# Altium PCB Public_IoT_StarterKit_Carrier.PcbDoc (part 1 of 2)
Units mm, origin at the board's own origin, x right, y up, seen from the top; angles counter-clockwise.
Board outline 84.62 x 84.55 mm, 4 copper layers (Top, PWR, MID, Bottom), stack 1.612 mm thick; 85 components, 101 nets, 416 pads, 114 vias.
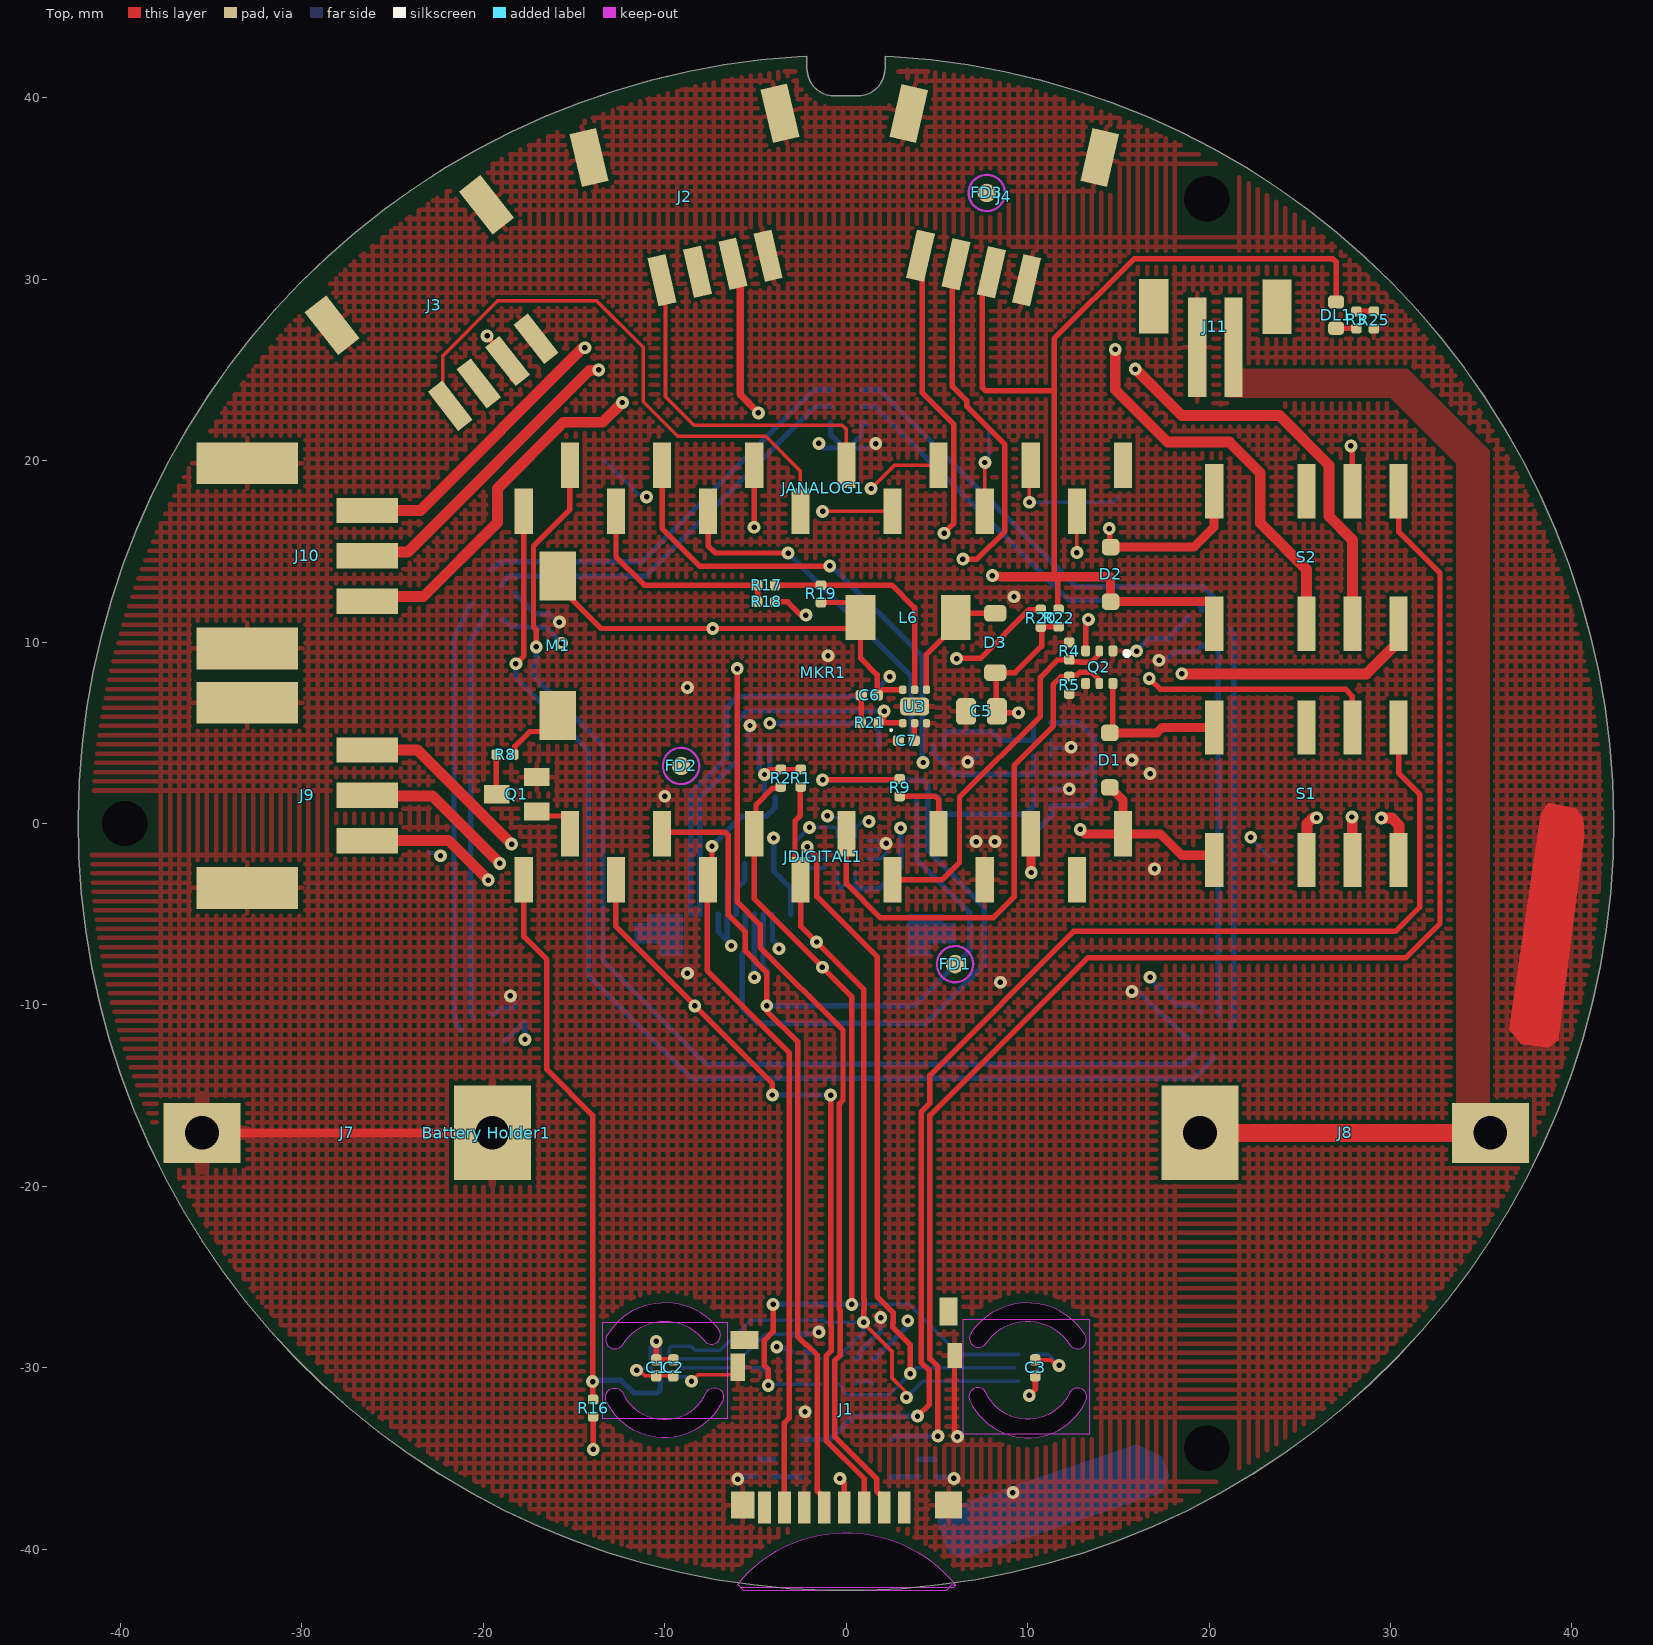
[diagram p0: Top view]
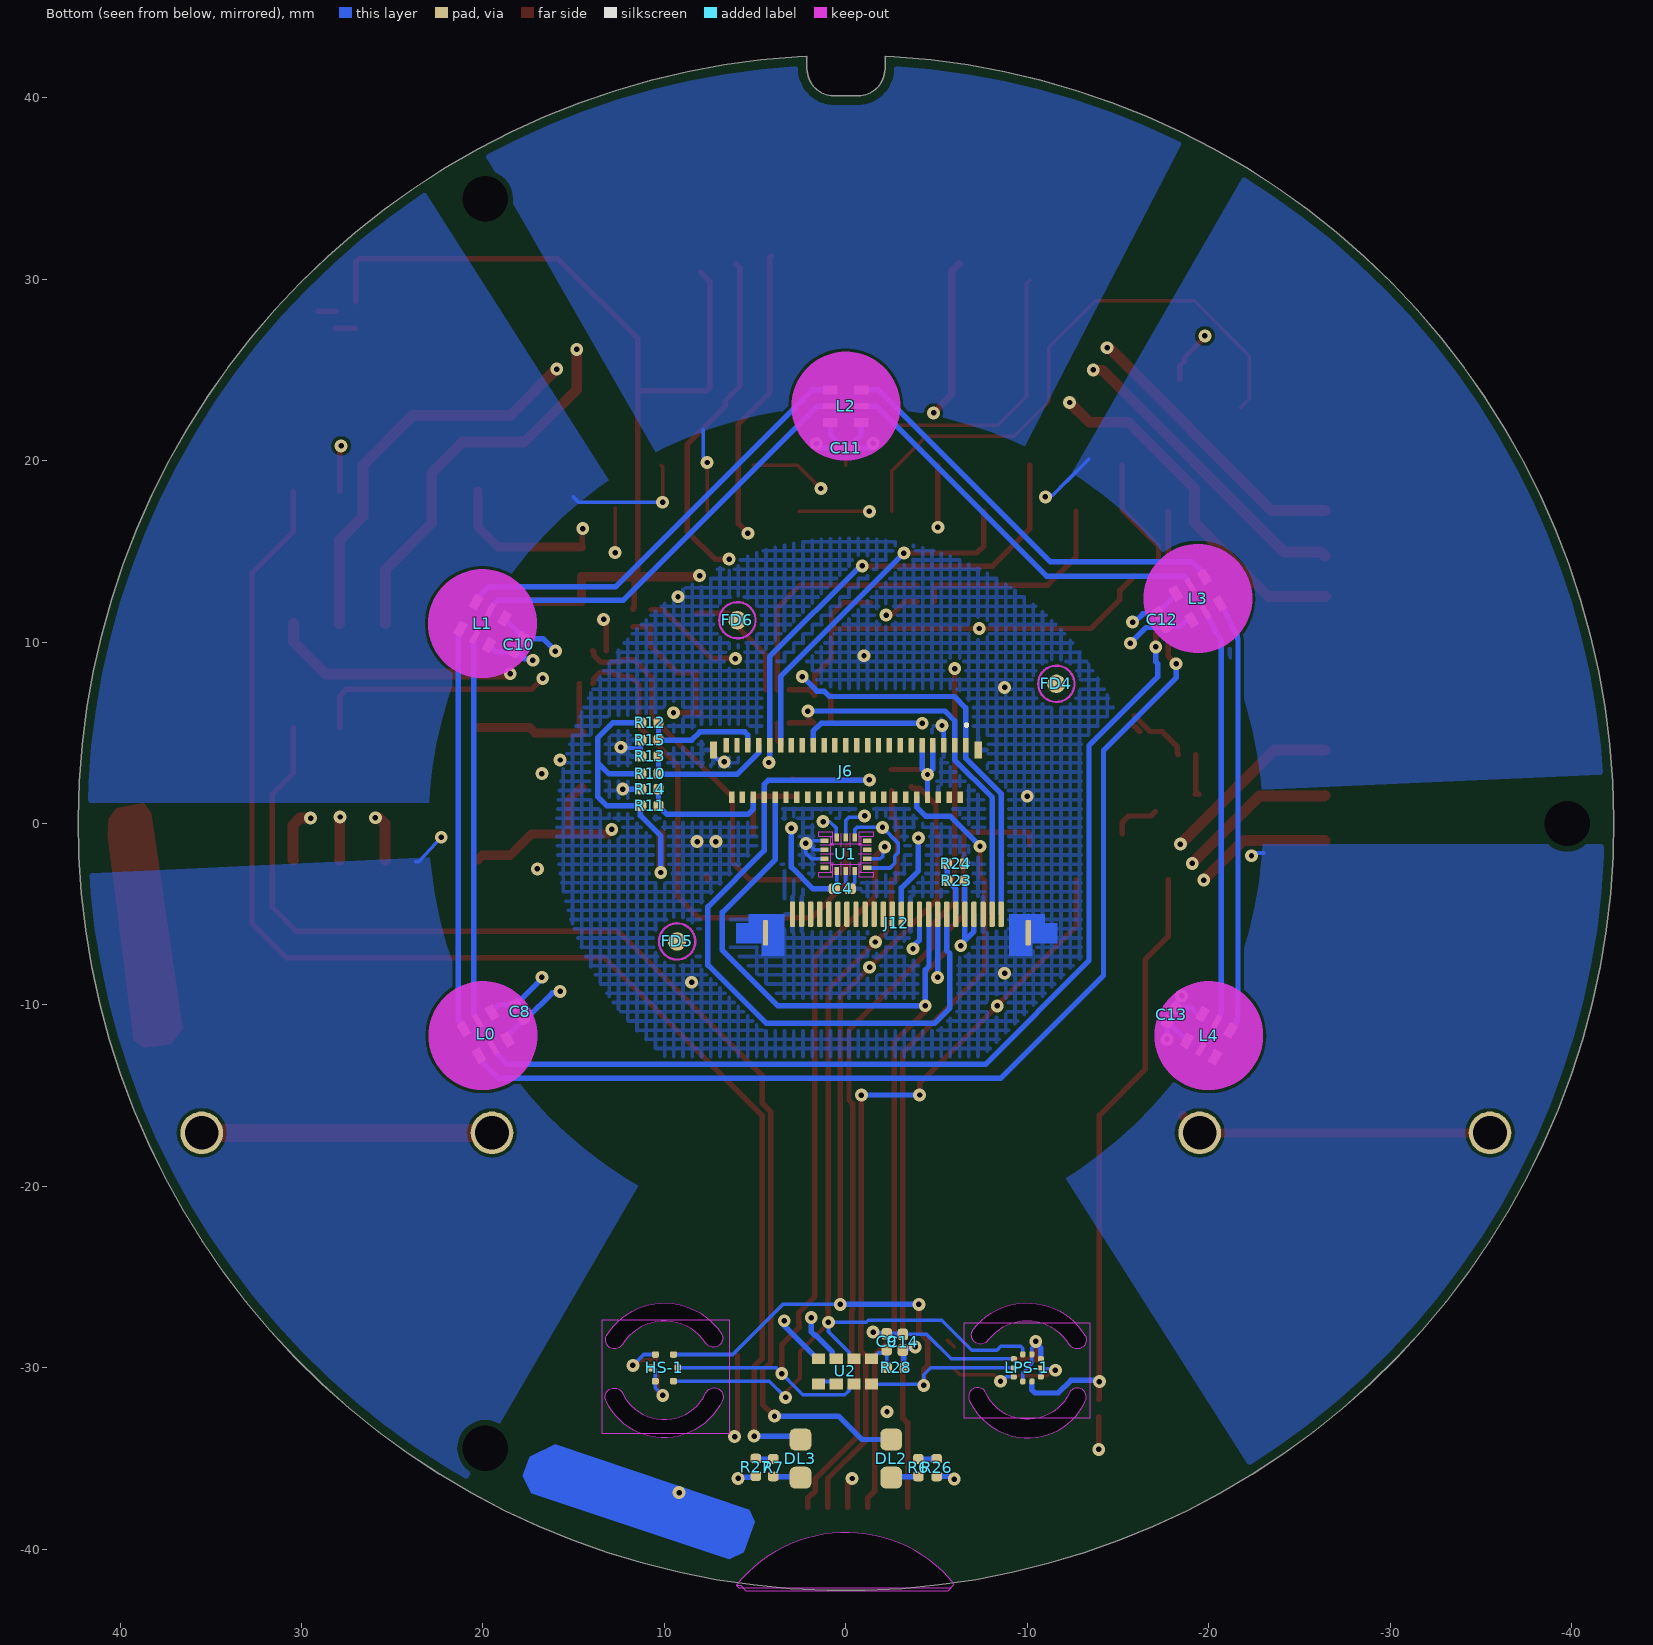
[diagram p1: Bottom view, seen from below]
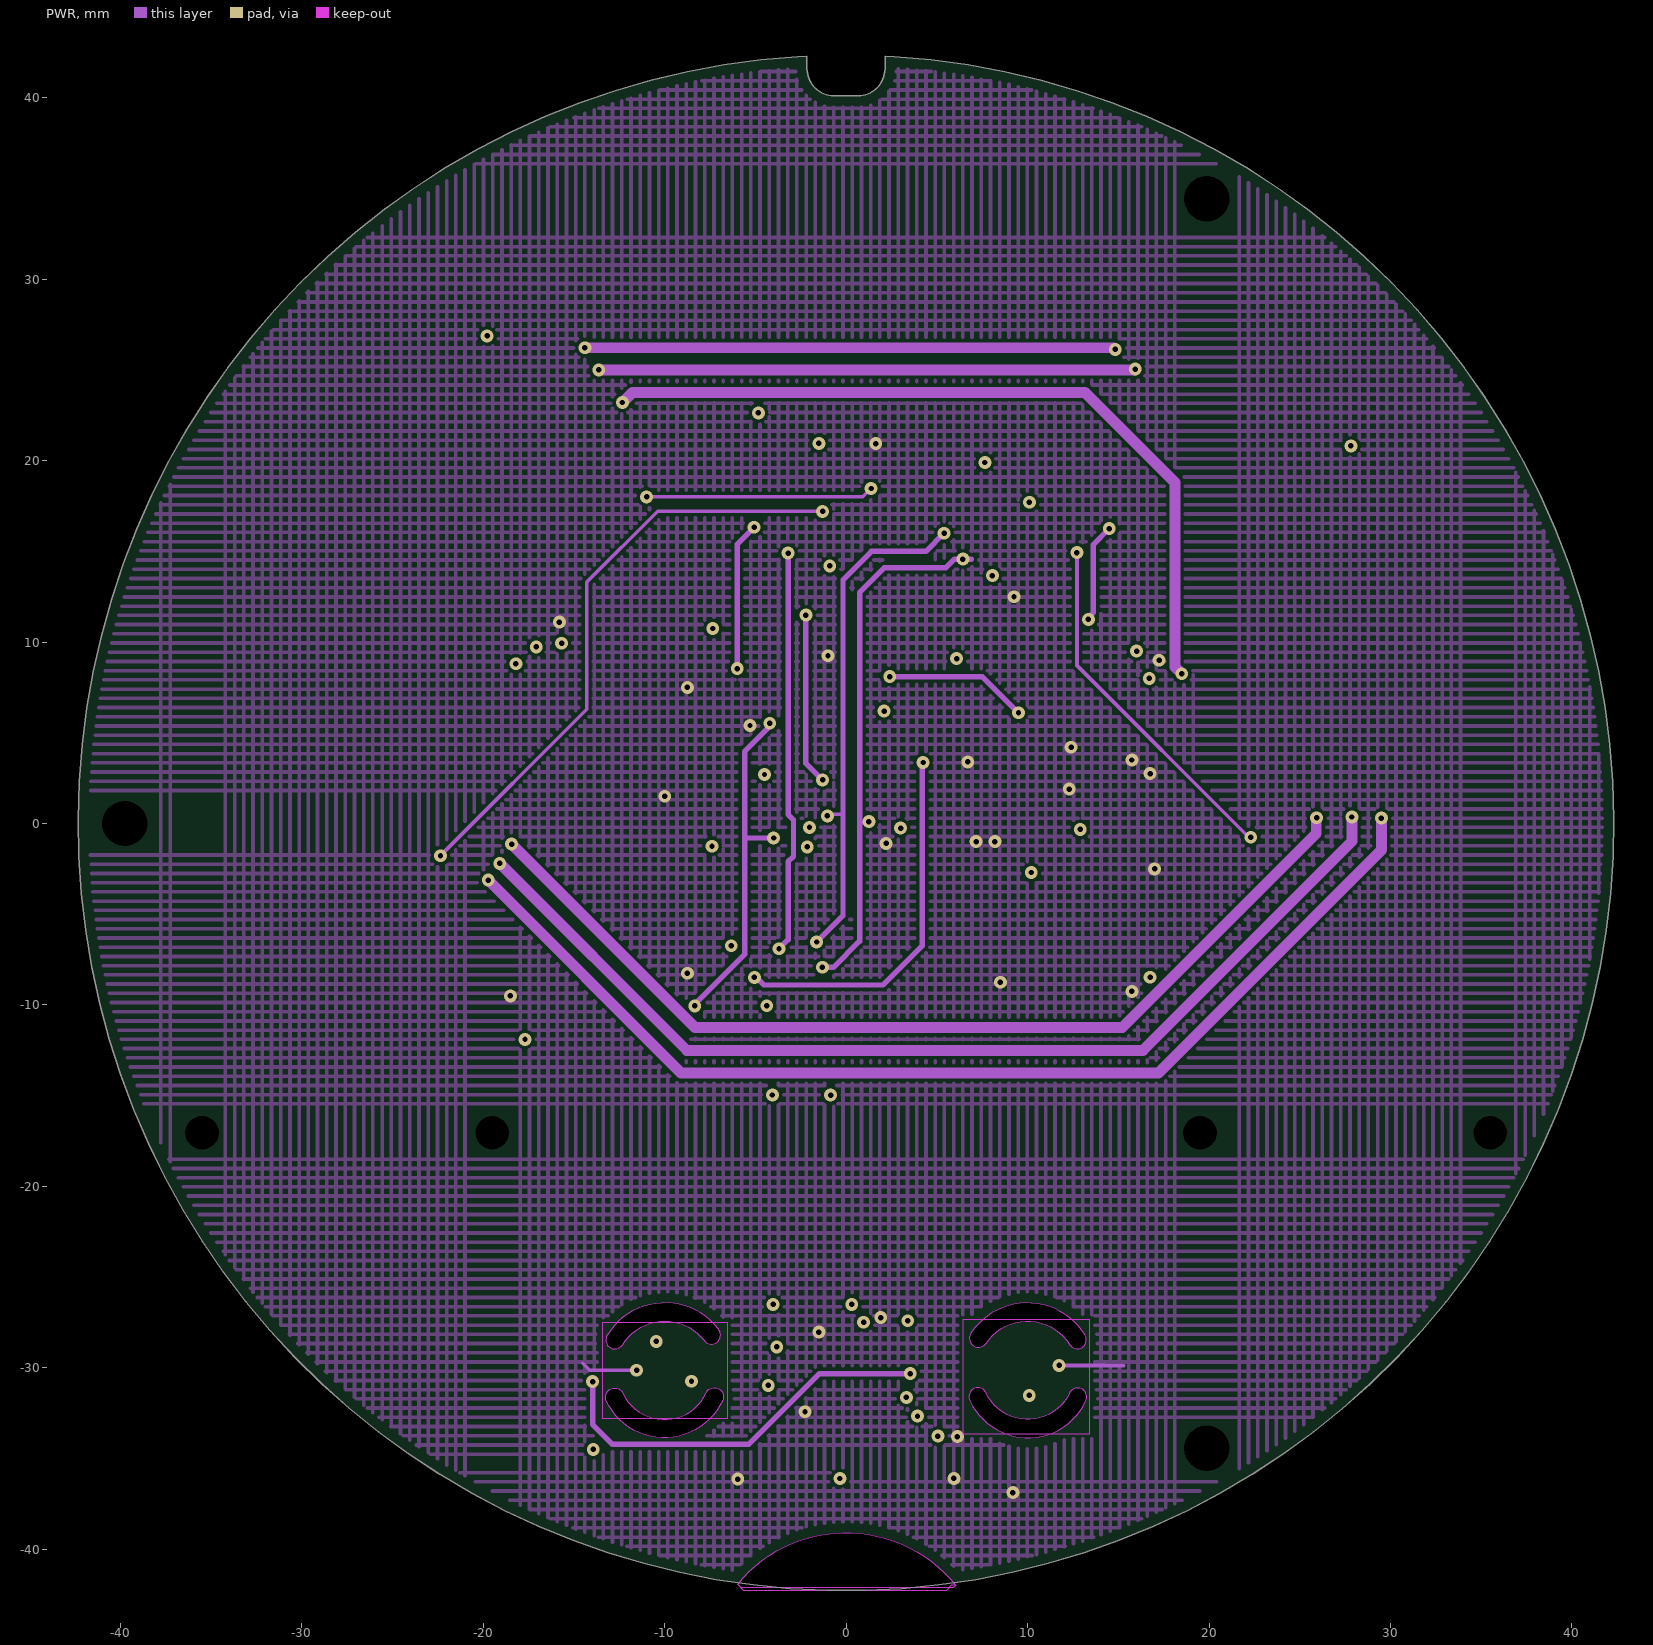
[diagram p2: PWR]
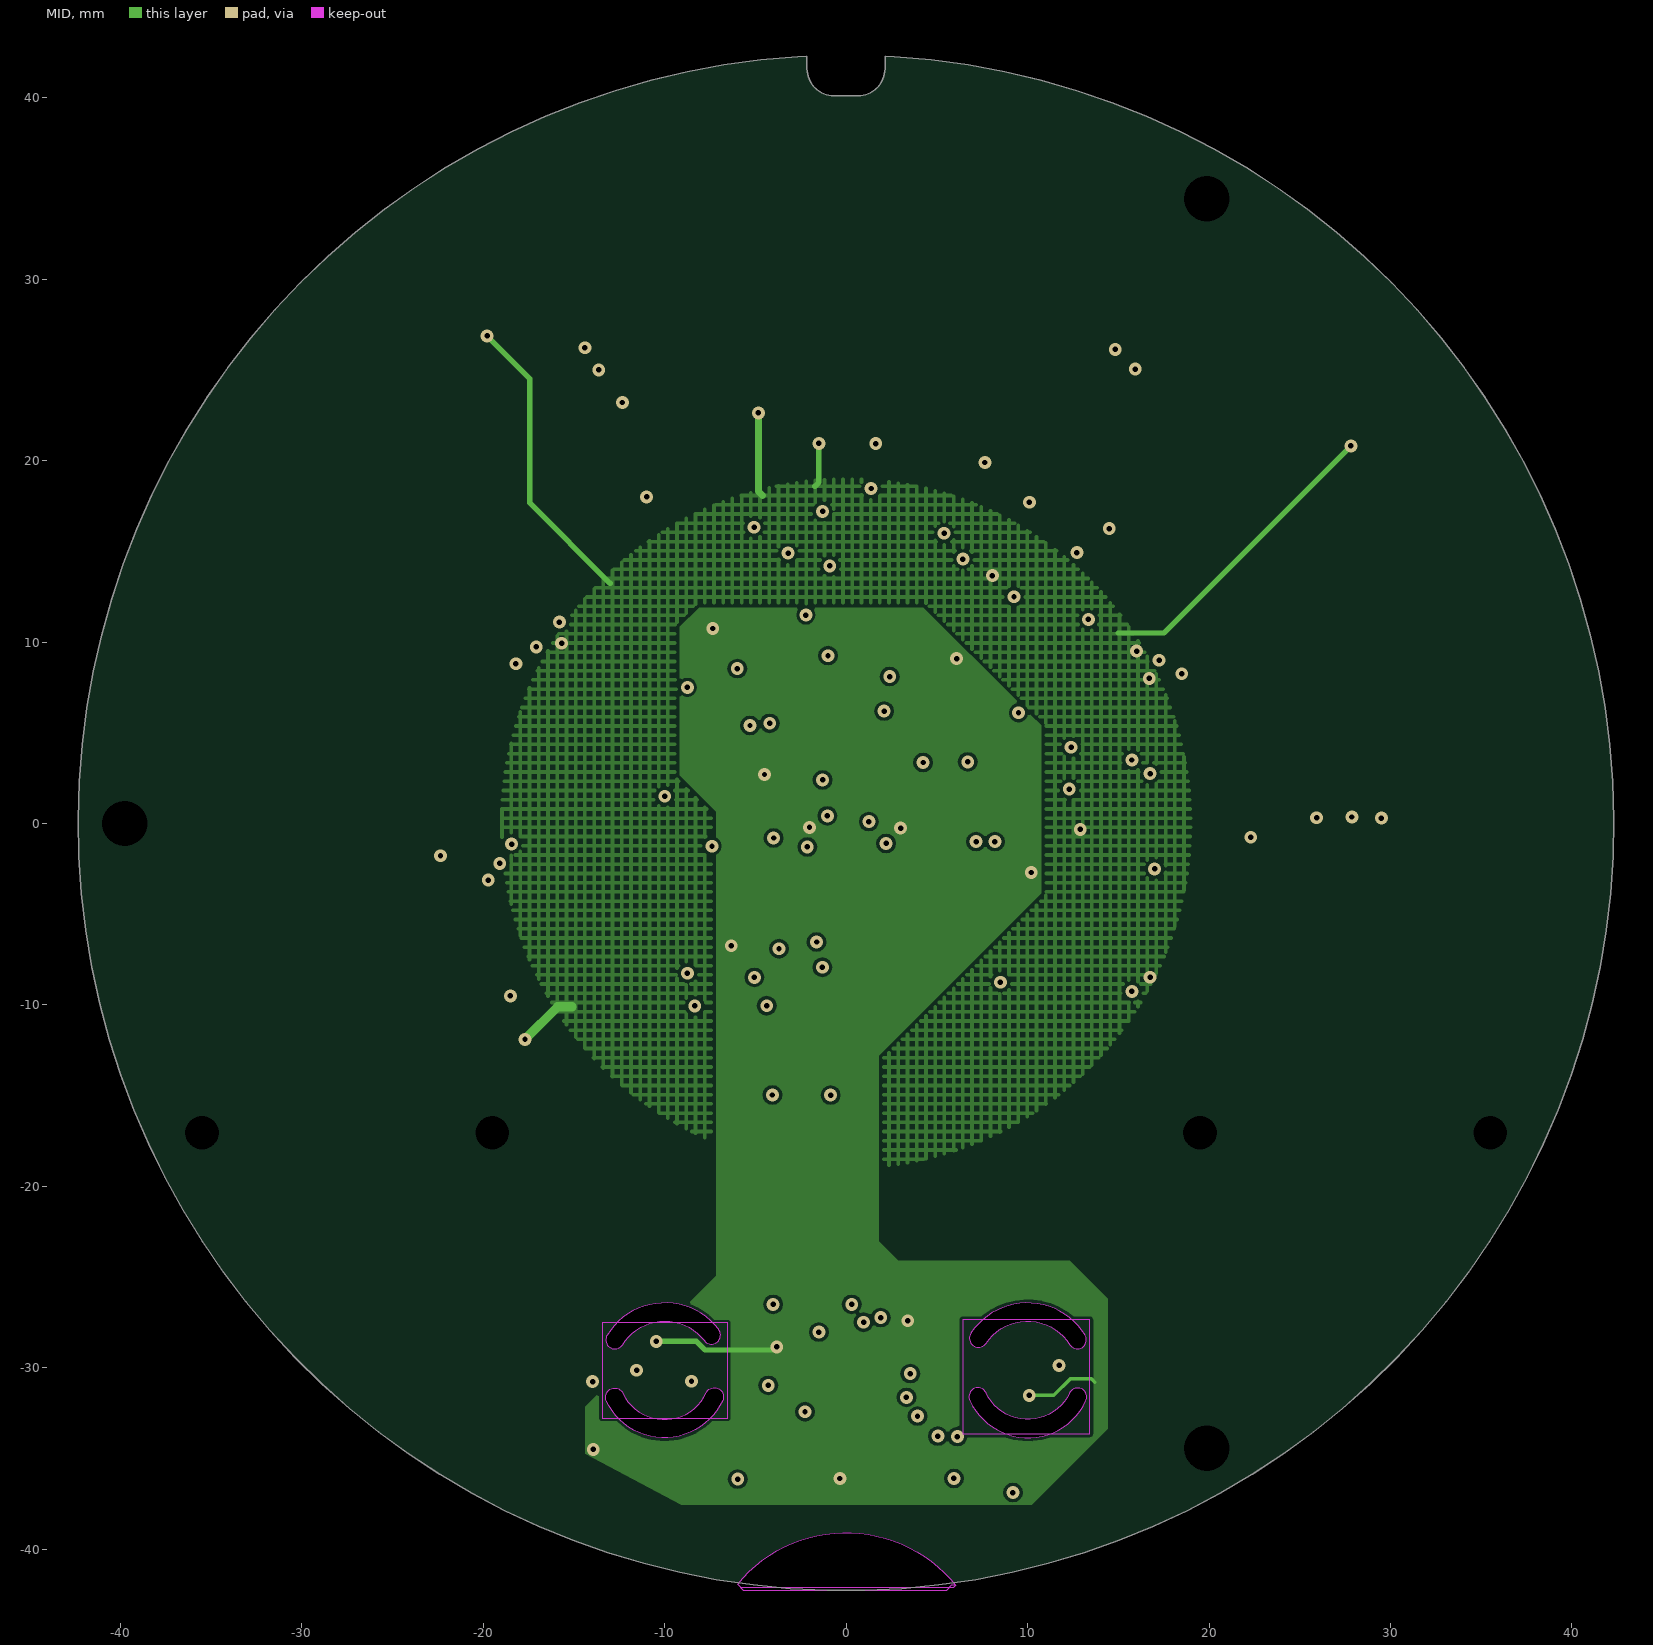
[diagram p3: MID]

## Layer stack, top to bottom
Top Solder: solder mask 0.01, Solder Resist, Dk 3.5
Top: signal copper 0.035
Dielectric 1: prepreg 0.356, FR-4, Dk 4.1
PWR: signal copper 0.035
Dielectric3: core 0.76, FR-4, Dk 4.8
MID: signal copper 0.035
Dielectric2: prepreg 0.356, FR-4, Dk 4.1
Bottom: signal copper 0.035
Bottom Solder: solder mask 0.0102, Solder Resist, Dk 3.5

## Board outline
-39.256,-15.774 -39.976,-13.853 -40.602,-11.9 -41.133,-9.918 -41.567,-7.914 -41.903,-5.89 -42.141,-3.853 -42.28,-1.806 -42.32,0.245 -42.26,2.295 -42.101,4.34 -41.843,6.375 -41.487,8.395 -41.033,10.396 -40.483,12.372 -39.837,14.319 -39.098,16.232 -38.267,18.108 -37.346,19.941 -36.338,21.727 -35.244,23.462 -34.067,25.142 -32.81,26.764 -31.477,28.322 -30.069,29.814 -28.59,31.236 -27.045,32.584 -25.435,33.856 -23.766,35.049 -22.042,36.159 -20.265,37.185 -18.441,38.123 -16.573,38.971 -14.667,39.728 -12.726,40.392 -10.755,40.961 -8.759,41.434 -6.743,41.809 -4.71,42.087 -2.667,42.265 -2.161,42.285 -2.161,41.593 -2.154,41.446 -2.099,41.169 -1.986,40.897 -1.822,40.652 -1.614,40.444 -1.369,40.28 -1.097,40.167 -0.82,40.112 -0.673,40.105 0.657,40.105 0.804,40.112 1.081,40.167 1.353,40.28 1.598,40.444 1.806,40.652 1.97,40.897 2.083,41.169 2.138,41.446 2.145,41.593 2.145,42.285 2.65,42.265 4.694,42.087 6.726,41.809 8.743,41.434 10.739,40.961 12.71,40.392 14.651,39.728 16.557,38.971 18.425,38.123 20.249,37.185 22.025,36.159 23.75,35.049 25.419,33.856 27.028,32.584 28.574,31.236 30.053,29.814 31.46,28.322 32.794,26.764 34.051,25.142 35.228,23.462 36.322,21.727 37.33,19.941 38.251,18.108 39.082,16.232 39.821,14.319 40.466,12.372 41.017,10.396 41.47,8.395 41.827,6.375 42.085,4.34 42.244,2.295 42.304,0.245 42.264,-1.806 42.125,-3.853 41.887,-5.89 41.551,-7.914 41.117,-9.918 40.586,-11.9 39.96,-13.853 39.24,-15.774 38.427,-17.657 37.525,-19.499 36.534,-21.295 35.457,-23.041 34.297,-24.733 33.056,-26.367 31.738,-27.938 30.344,-29.444 28.88,-30.88 27.348,-32.244 25.751,-33.532 24.094,-34.741 22.38,-35.868 20.614,-36.911 18.799,-37.867 16.94,-38.734 15.041,-39.509 13.107,-40.192 11.142,-40.781 9.15,-41.273 7.138,-41.668 5.108,-41.966 3.066,-42.164 1.018,-42.264 -1.034,-42.264 -3.083,-42.164 -5.124,-41.966 -7.154,-41.668 -9.167,-41.273 -11.158,-40.781 -13.123,-40.192 -15.057,-39.509 -16.956,-38.734 -18.815,-37.867 -20.63,-36.911 -22.396,-35.868 -24.11,-34.741 -25.767,-33.532 -27.364,-32.244 -28.896,-30.88 -30.361,-29.444 -31.754,-27.938 -33.072,-26.367 -34.313,-24.733 -35.473,-23.041 -36.55,-21.295 -37.541,-19.499 -38.443,-17.657
cut-out: -13.171,-28.197 ccw(c-12.745,-28.459) -12.319,-28.722 cw(c-9.991,-30.158) -7.821,-28.492 ccw(c-7.424,-28.187) -6.924,-28.187 ccw(c-7.424,-28.187) -7.027,-27.882 ccw(c-9.991,-30.158)
cut-out: -6.808,-31.803 cw(c-10.016,-30.312) -13.214,-31.825 cw(c-12.761,-31.611) -13.262,-31.611 cw(c-12.761,-31.611) -12.309,-31.397 ccw(c-10.016,-30.312) -7.715,-31.381 cw(c-7.262,-31.592)
cut-out: 6.808,-31.803 ccw(c10.016,-30.312) 13.214,-31.825 ccw(c12.761,-31.611) 13.262,-31.611 ccw(c12.761,-31.611) 12.309,-31.397 cw(c10.016,-30.312) 7.715,-31.381 ccw(c7.262,-31.592)
cut-out: 6.876,-28.094 ccw(c7.293,-28.37) 7.71,-28.647 cw(c9.991,-30.158) 12.319,-28.722 ccw(c12.745,-28.459) 13.245,-28.459 ccw(c12.745,-28.459) 13.171,-28.197 ccw(c9.991,-30.158)
cut-out: -5.63,-42.274 -5.983,-41.921 cw(c0,-46.8) 6.037,-41.989 5.805,-41.989 5.519,-42.274
cut-out: -5.783,-42.12 -5.983,-41.921 cw(c0,-46.8) 6.037,-41.989 5.896,-42.13

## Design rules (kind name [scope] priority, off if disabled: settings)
BoardOutlineClearance BoardOutlineClearance_1 [IsPolygon] p1: gap=0.5 ignorepadtopadclearanceinfootprint=FALSE
Clearance "Clearance (Same Net)" [All] p1 off: gap=0.178 ignorepadtopadclearanceinfootprint=TRUE except(0.152: SMDPad-SMDPad SMDPad-THPad SMDPad-Via)
Clearance [All] p2: gap=0.178 ignorepadtopadclearanceinfootprint=TRUE except(0.3: THPad-Fill THPad-Poly THPad-Region)
HoleSize [All] p1: absolutevalues=TRUE maxlimit=2540 minlimit=0.3 maxpercent=80.000 minpercent=20.000
HoleToHoleClearance mdDrill [All] p1: gap=0.254 allowstackedmicrovias=TRUE
MinimumSolderMaskSliver [All] p1 off: minsoldermaskwidth=0.1
PasteMaskExpansion Expansion_SMDPaste_OFF [InPadClass('SMDPaste_OFF')] p1: expansion=0
PasteMaskExpansion mlMinCreamFrame [All] p2: expansion=0
PolygonConnect PolygonConnect_For_PolygonThermal_ON_Width120000_Gap100000 [InPolygonClass('PolygonThermal_ON_Width120000_Gap100000')] p1: connectstyle=Relief reliefconductorwidth=0.305 reliefentries=4 polygonreliefangle="90 Angle" airgapwidth=0.254
PolygonConnect PolygonConnect_For_PolygonThermal_OFF [InPolygonClass('PolygonThermal_OFF')] p2: connectstyle=Direct reliefconductorwidth=0.254 reliefentries=4 polygonreliefangle="90 Angle" airgapwidth=0.254
PolygonConnect PolygonConnect_For_PolygonThermal_ON_Width160000_Gap100000 [InPolygonClass('PolygonThermal_ON_Width160000_Gap100000')] p3: connectstyle=Relief reliefconductorwidth=0.406 reliefentries=4 polygonreliefangle="90 Angle" airgapwidth=0.254
PolygonConnect ThermalVias [IsVia] p4: connectstyle=Direct reliefconductorwidth=0.254 reliefentries=4 polygonreliefangle="90 Angle" airgapwidth=0.254
PolygonConnect [All] p5: connectstyle=Relief reliefconductorwidth=0.254 reliefentries=4 polygonreliefangle="90 Angle" airgapwidth=0.254
RoomDefinition SD-Card [InComponentClass('SD-Card')] p1 off: confinementstyle=ConfineIn formatcopy=TRUE lockcomponents=FALSE outline -290.242,-353.781 -239.442,-353.781 -239.442,-328.381 -290.242,-328.381
RoomDefinition "SC_capacitive buttons_6" [InComponentClass('SC_capacitive buttons_6')] p2 off: confinementstyle=ConfineIn formatcopy=TRUE lockcomponents=FALSE outline -290.242,-353.781 -239.442,-353.781 -239.442,-328.381 -290.242,-328.381
RoomDefinition Relays [InComponentClass('Relays')] p3 off: confinementstyle=ConfineIn formatcopy=TRUE lockcomponents=FALSE outline -290.242,-353.781 -239.442,-353.781 -239.442,-328.381 -290.242,-328.381
RoomDefinition OLED [InComponentClass('OLED')] p4 off: confinementstyle=ConfineIn formatcopy=TRUE lockcomponents=FALSE outline 43.957,-34.181 69.057,-34.181 69.057,-29.981 43.957,-29.981
RoomDefinition APDS-9306-065 [InComponentClass('APDS-9306-065')] p5 off: confinementstyle=ConfineIn formatcopy=TRUE lockcomponents=FALSE outline 43.957,-41.381 48.357,-41.381 48.357,-35.581 43.957,-35.581
RoomDefinition ABT-461-RC [InComponentClass('ABT-461-RC')] p6 off: confinementstyle=ConfineIn formatcopy=TRUE lockcomponents=FALSE outline -290.242,-353.781 -239.442,-353.781 -239.442,-328.381 -290.242,-328.381
RoomDefinition "IMU sensor" [InComponentClass('IMU sensor')] p7 off: confinementstyle=ConfineIn formatcopy=TRUE lockcomponents=FALSE outline -147.842,-244.081 -144.042,-244.081 -144.042,-239.481 -147.842,-239.481
RoomDefinition Controller [InComponentClass('Controller')] p8 off: confinementstyle=ConfineIn formatcopy=TRUE lockcomponents=FALSE outline -290.242,-353.781 -239.442,-353.781 -239.442,-328.381 -290.242,-328.381
RoomDefinition "Humidity/Temp Sensor" [InComponentClass('Humidity/Temp Sensor')] p9 off: confinementstyle=ConfineIn formatcopy=TRUE lockcomponents=FALSE outline -231.142,-341.181 -228.342,-341.181 -228.342,-337.181 -231.142,-337.181
RoomDefinition "Barometric Sensor" [InComponentClass('Barometric Sensor')] p10 off: confinementstyle=ConfineIn formatcopy=TRUE lockcomponents=FALSE outline -231.142,-346.481 -225.142,-346.481 -225.142,-342.481 -231.142,-342.481
RoomDefinition TOP [InComponentClass('TOP')] p11 off: confinementstyle=ConfineIn formatcopy=TRUE lockcomponents=FALSE outline -278.142,-341.681 -252.442,-341.681 -252.442,-273.381 -278.142,-273.381
RoutingVias [All] p1: holewidth=0.3 width=0.706 viastyle="Through Hole" minholewidth=0.3 minwidth=0.706 maxholewidth=2.54 maxwidth=2.54
SilkToSilkClearance [All] p1 off: silktosilkclearance=0.254
SilkToSolderMaskClearance [IsPad] p1 off: minsilkscreentomaskgap=0.1 clearancetoexposedcopper=TRUE
SolderMaskExpansion Expansion_SMDSolder_OFF [InPadClass('SMDSolder_OFF')] p1: expansion=0 istentingtop=FALSE
SolderMaskExpansion mlMinStopFrame [All] p2: expansion=0.1 istentingtop=FALSE
Width [All] p1: maxlimit=254 minlimit=0.2 preferedwidth=0.3
24 further rules are at their usual default settings.

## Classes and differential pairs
component class SD-Card: J1
component class OLED: C5 C6 C7 D3 J6 J12 L6 R10 R11 R12 R13 R14 R15 R19 R20 R21 R22 R23 R24 U3
component class APDS-9306-065: C9 C14 R28 U2
component class ABT-461-RC: M1 Q1 R8
component class TOP: "Battery Holder1" DL1 FD1 FD2 FD3 FD4 FD5 FD6 J2 J3 J4 J7 J8 J11 R3 R9 R16 R17 R18 R25
component class "IMU sensor": C4 U1
component class Relays: D1 D2 DL2 DL3 J9 J10 Q2 R4 R5 R6 R7 R26 R27 S1 S2
component class "Humidity/Temp Sensor": C3 HS-1
component class "Barometric Sensor": C1 C2 LPS-1
component class "SC_capacitive buttons_6": C8 C10 C11 C12 C13 L0 L1 L2 L3 L4
component class Controller: JANALOG1 JDIGITAL1 MKR1 R1 R2

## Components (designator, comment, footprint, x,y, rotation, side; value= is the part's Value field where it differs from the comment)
"Battery Holder1" "Battery Holder" "Battery Holder-Footprint-1" -19.834,-17.049 r0 top
C1 "C0402C103K3RACTU" CAP-0402 -10.465,-30 r270 top value=10nF
C2 "GRM155R60J475ME47D" CAP-0402 -9.519,-30 r90 top value=4.7µF
C3 "C0402C104K3PACTU" CAP-0402 10.425,-30 r270 top value=100nF
C4 "C0402C104K3PACTU" CAP-0402 0.2,-3.6 r0 bottom value=100nF
C5 "GCM21BC72A105KE36L" CAP-0805 7.458,6.178 r0 top value=1µF
C6 "C0402C105M9PACTU" CAP-0402 1.273,7.073 r0 top value=1µF
C7 "C0402C224K9PACTU" CAP-0402 3.319,4.57 r0 top value=220nF
C8 "C0402C104K3PACTU" CAP-0402 17.98,-10.38 r60 bottom value=100nF
C9 "C0402C105K4PACTU" CAP-0402 -2.25,-28.565 r270 bottom value=1µF
C10 "C0402C104K3PACTU" CAP-0402 18.034,9.844 r120 bottom value=100nF
C11 "C0402C104K3PACTU" CAP-0402 -0.003,20.694 r180 bottom value=100nF
C12 "C0402C104K3PACTU" CAP-0402 -17.419,11.228 r240 bottom value=100nF
C13 "C0402C104K3PACTU" CAP-0402 -17.936,-10.548 r300 bottom value=100nF
C14 "C0402C105K4PACTU" CAP-0402 -3.139,-28.591 r90 bottom value=1µF
D1 "PMEG6020ER,115" SOD123 14.534,3.49 r90 top
D2 "PMEG6020ER,115" SOD123 14.576,13.73 r90 top
D3 "1N4148W" SOD123-1 8.219,9.955 r90 top
DL1 "HSMG-C190" LEDC1608X80N-AK 27,28.018 r90 top
DL2 "KPT-2012YC" CHIPLED_0805 -2.5,-35 r270 bottom
DL3 "KPT-2012YC" CHIPLED_0805 2.5,-35 r270 bottom
FD1 "Fiducial mark 1.5mm" FIDUCIAL-1.5 6,-7.75 r0 top
FD2 "Fiducial mark 1.5mm" FIDUCIAL-1.5 -9.1,3.174 r0 top
FD3 "Fiducial mark 1.5mm" FIDUCIAL-1.5 7.75,34.75 r0 top
FD4 "Fiducial mark 1.5mm" FIDUCIAL-1.5 -11.6,7.7 r180 bottom
FD5 "Fiducial mark 1.5mm" FIDUCIAL-1.5 9.3,-6.5 r180 bottom
FD6 "Fiducial mark 1.5mm" FIDUCIAL-1.5 5.975,11.202 r180 bottom
HS-1 "HTS221" HTS221 10,-30 r180 bottom
J1 "114-00841-68" AMPHENOL_114-00841-68 -0.002,-31.806 r0 top
J2 "320110032" 320110032-Footprint-1 -7.243,30.718 r13 top
J3 "320110032" 320110032-Footprint-1 -19.519,24.95 r38 top
J4 "320110032" 320110032-Footprint-1 7.051,30.704 r347 top
J6 "FH26W-45S-0.3SHW(60)" FH26W-45S-0.3SHW(60)-Footprint-1 0,3 r0 bottom
J7 "254TR" 254TR-Footprint-1 -35.5,-17.049 r0 top
J8 "254TR" 254TR-Footprint-1 35.5,-17.049 r180 top
J9 "1771033" 1771033-Footprint-1 -33,1.55 r270 top
J10 "1771033" 1771033-Footprint-1 -33,14.75 r270 top
J11 "B2B-PH-SM4-TB(LF)(SN)" "New footprint 1" 20.353,31 r0 top
J12 "SFV24R-1STBE1HLF" SFV24R-1STBE1HLF-Footprint-1 -2.81,-5 r180 bottom locked
JANALOG1 "MKR-SMD-AREF" 21TW-332-Footprint-1 15.256,19.751 r180 top locked
JDIGITAL1 "MKR-SMD-5V" 21TW-331-Footprint-1 -17.764,-0.569 r180 top locked
L0 "APA1022020-2018" APA102-2020-Footprint-1 19.856,-11.611 r60 bottom
L1 "APA1022020-2018" APA102-2020-Footprint-1 20.028,11.015 r120 bottom
L2 "APA1022020-2018" APA102-2020-Footprint-1 0,23 r180 bottom
L3 "APA1022020-2018" APA102-2020-Footprint-1 -19.4,12.4 r240 bottom
L4 "APA1022020-2018" APA102-2020-Footprint-1 -20,-11.691 r300 bottom
L6 "SRR0604-100ML" SRR0604-100ML-Footprint-1 3.416,11.351 r0 top
LPS-1 "LPS22HBTR" LPS22H -10,-30 r0 bottom
M1 "ABT-461-RC" ABT-461-RC-Footprint-1 -15.902,9.8 r270 top
MKR1 "MKRBOARD-SMD-ALTERNATE" MKRSHIELD 37.452,20.819 r180 top locked
Q1 "2N7002KT1G" SOT23 -18.161,1.609 r90 top
Q2 "BSS138PS" SOT363 13.949,8.615 r180 top
R1 "CRCW040210K0JNED" RES-0402 -2.5,2.5 r90 top value=10k
R2 "CRCW040210K0JNED" RES-0402 -3.6,2.5 r90 top value=10k
R3 "CRCW0402330RJNED" RES-0402 28.118,27.753 r270 top value=330
R4 "CRCW040210K0JNED" RES-0402 12.298,9.506 r90 top value=10k
R5 "CRCW040210K0JNED" RES-0402 12.298,7.618 r270 top value=10k
R6 "RC0402JR-07270RL" RES-0402 -4,-35.5 r270 bottom value=270
R7 "RC0402JR-07270RL" RES-0402 4,-35.5 r270 bottom value=270
R8 "CRCW04020000Z0EDC" RES-0402 -18.8,3.8 r0 top value=0
R9 "CRCW04020000Z0EDC" RES-0402 2.95,1.975 r270 top value=0
R10 "CRCW040210K0JNED" RES-0402 10.8,2.749 r0 bottom value=10k
R11 "CRCW040210K0JNED" RES-0402 10.8,0.973 r0 bottom value=10k
R12 "CRCW040210K0JNED" RES-0402 10.8,5.547 r0 bottom value=10k
R13 "CRCW04020000Z0EDC" RES-0402 10.8,3.695 r180 bottom value=0
R14 "CRCW04020000Z0EDC" RES-0402 10.8,1.9 r180 bottom value=0
R15 "CRCW04020000Z0EDC" RES-0402 10.8,4.6 r180 bottom value=0
R16 "CRCW040210K0JNED" RES-0402 -13.949,-32.218 r270 top value=10k
R17 "CRCW04020000Z0EDC" RES-0402 -4.399,13.132 r0 top value=0
R18 "CRCW04020000Z0EDC" RES-0402 -4.399,12.215 r0 top value=0
R19 "CRCW040210K0JNED" RES-0402 -1.386,12.655 r270 top value=10k
R20 "CRCW04020000Z0EDC" RES-0402 10.73,11.309 r90 top value=0
R21 "RC0402FR-0710RL" RES-0402 1.306,5.55 r0 top value=10
R22 "CRCW04020000Z0EDC" RES-0402 11.712,11.322 r270 top value=0
R23 "CRCW040210K0JNED" RES-0402 -6.072,-3.144 r180 bottom value=10k
R24 "CRCW04020000Z0EDC" RES-0402 -6.052,-2.212 r0 bottom value=0
R25 "CRCW04020000Z0EDC" RES-0402 29.084,27.748 r90 top value=0
R26 "CRCW04020000Z0EDC" RES-0402 -5,-35.5 r90 bottom value=0
R27 "CRCW04020000Z0EDC" RES-0402 4.958,-35.483 r90 bottom value=0
R28 "RC0402FR-0722RL" RES-0402 -2.75,-30 r180 bottom value=22
S1 "EE2-5NU-L" EE2-5NU-L-Footprint-1 26.234,1.64 r90 top locked
S2 "EE2-5NU-L" EE2-5NU-L-Footprint-1 26.234,14.665 r90 top
U1 "LSM6DS3TR" VFLGA14 0,-1.7 r180 bottom
U2 "APDS-9660" APDS-9660-Footprint-1 0.045,-30.2 r0 bottom
U3 "LV52204MTTBG" QFN65P200X200X80_HS-7L 3.775,6.448 r0 top

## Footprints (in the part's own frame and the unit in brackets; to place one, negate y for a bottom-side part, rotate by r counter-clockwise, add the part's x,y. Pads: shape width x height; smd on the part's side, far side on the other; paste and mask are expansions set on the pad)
21TW-331-Footprint-1 [mm]
  rect 1x2.5 smd: 1(0,2.54) 2(-2.54,0) 4(-7.62,0) 5(-10.16,2.54) 6(-12.7,0) 7(-15.24,2.54) 8(-17.78,0) 9(-20.32,2.54) 10(-22.86,0) 11(-25.4,2.54) 12(-27.94,0) 13(-30.48,2.54) 14(-33.02,0) ""(-5.08,2.54)
  body extent -34.29,-1.02 1.27,3.56, height 9.39
21TW-332-Footprint-1 [mm]
  rect 1x2.5 smd: 1(0,0) 2(2.54,2.54) 3(5.08,0) 4(7.62,2.54) 5(10.16,0) 6(12.7,2.54) 7(15.24,0) 8(17.78,2.54) 9(20.32,0) 10(22.86,2.54) 11(25.4,0) 12(27.94,2.54) 13(30.48,0) 14(33.02,2.54)
  body extent -1.27,-1.02 34.29,3.56, height 9.39
254TR-Footprint-1 [mm]
  rect 0x0 hole 1.85 unplated: 1(0,0) -(16,0)
  rect 4.24x3.3 smd: 1(0,0)
  rect 4.24x5.2 smd: 2(16,0)
  body extent 0.6,-9.3 14.4,9.3, height 19.8
1771033-Footprint-1 [mm]
  rect 1.4x3.4 smd: 1(-2.5,6.6) 2(0,6.6) 3(2.5,6.6)
  rect 2.3x5.6 smd: MP1(-5.1,0) MP2(5.1,0)
  body extent -5.95,-3.6 5.95,7.4, height 5.01
320110032-Footprint-1 [mm]
  rect 1.01x2.74 smd: 1(-3,-0.1) 2(-1,-0.1) 3(1,-0.1) 4(3,-0.1)
  rect 1.5x3 smd: SS1(-5.4,7.4) SS2(5.4,7.4)
  body extent -6,-1.14 6,8.81, height 5.01
ABT-461-RC-Footprint-1 [mm]
  rect 2.7x2 smd: 1(-3.85,0) 2(3.85,0)
  body extent -5.25,-4.63 5.25,5.87, height 2.67
AMPHENOL_114-00841-68 [mm]
  rect 0.7x1.75 smd: 1(3.2,-5.888) 2(2.1,-5.888) 3(1,-5.888) 4(-0.1,-5.888) 5(-1.2,-5.888) 6(-2.3,-5.888) 7(-3.4,-5.888) 8(-4.5,-5.888)
  rect 1x1.55 smd: CD1(5.65,4.912)
  rect 1.55x1 smd: CD2(-5.602,3.337)
  rect 1.3x1.5 smd: SH1(-5.7,-5.76)
  rect 1.5x1.5 smd: SH2(5.65,-5.76)
  rect 0.8x1.4 smd: SH3(5.975,2.487)
  rect 0.8x1.5 smd: SH4(-5.975,1.837)
  body extent -6,-10.29 6,4.99, height 1.6
APA102-2020-Footprint-1 [mil]
  rect 31.5x19.69 smd: 1(33.46,35.43) 3(33.46,-35.43) 4(-33.46,-35.43) 6(-33.46,35.43)
  rect 31.5x11.81 smd: 2(33.46,0) 5(-33.46,0)
  body extent -39,-39 44,39, height 36
APDS-9660-Footprint-1 [mm]
  rect 0.72x0.6 smd: 1(-1.455,0.7) 2(-0.485,0.7) 3(0.485,0.7) 4(1.455,0.7) 5(1.455,-0.7) 6(0.485,-0.7) 7(-0.485,-0.7) 8(-1.455,-0.7)
  body extent -1.97,-1.18 1.97,1.18, height 1.3
"Battery Holder-Footprint-1" [mm]
CAP-0402 [mm] "Chip Capacitor, 2-Leads, Body  0402 (in) 1005 (mm), IPC Medium Density"
  rrect52% 0.63x0.58 smd mask+0: 1(-0.435,0) 2(0.435,0)
  body extent -0.5,-0.25 0.5,0.25, height 0.5
CAP-0805 [mm] "Chip Capacitor, Body 0805 imperial, 2.0x1.2mm, IPC Medium Density"
  rrect45% 1.11x1.47 smd mask+0: 1(-0.85,0) 2(0.85,0)
  body extent -1,-0.62 1,0.63, height 1.25
CHIPLED_0805 [mm]
  rrect50% 1.2x1.2 smd: A(-1.05,0) C(1.05,0)
  body extent -1.04,-0.45 1.02,0.46, height 0.85
EE2-5NU-L-Footprint-1 [mm]
  rect 3x1 smd: 1(-3.65,5.95) 3(-3.65,0.87) 4(-3.65,-1.67) 5(-3.65,-4.21) 8(3.65,-4.21) 9(3.65,-1.67) 10(3.65,0.87) 12(3.65,5.95)
  body extent -4.7,-7.75 4.8,7.25, height 10.01
FH26W-45S-0.3SHW(60)-Footprint-1 [mm]
  rect 0.3x0.8 smd: 1(-6.6,-1.325) 3(-6,-1.325) 5(-5.4,-1.325) 7(-4.8,-1.325) 9(-4.2,-1.325) 11(-3.6,-1.325) 13(-3,-1.325) 15(-2.4,-1.325) 17(-1.8,-1.325) 19(-1.2,-1.325) 21(-0.6,-1.325) 23(0,-1.325) 25(0.6,-1.325) 27(1.2,-1.325) 29(1.8,-1.325) 31(2.4,-1.325) 33(3,-1.325) 35(3.6,-1.325) 37(4.2,-1.325) 39(4.8,-1.325) 41(5.4,-1.325) 43(6,-1.325) 45(6.6,-1.325)
  rect 0.3x0.65 smd: 2(-6.3,1.55) 4(-5.7,1.55) 6(-5.1,1.55) 8(-4.5,1.55) 10(-3.9,1.55) 12(-3.3,1.55) 14(-2.7,1.55) 16(-2.1,1.55) 18(-1.5,1.55) 20(-0.9,1.55) 22(-0.3,1.55) 24(0.3,1.55) 26(0.9,1.55) 28(1.5,1.55) 30(2.1,1.55) 32(2.7,1.55) 34(3.3,1.55) 36(3.9,1.55) 38(4.5,1.55) 40(5.1,1.55) 42(5.7,1.55) 44(6.3,1.55)
  rect 0.4x0.95 smd: MP1(-7.3,-1.05) MP2(7.3,-1.05)
  silkscreen extent -6.7,-2.47 -6.6,-2.38, body extent -7.5,-1.7 7.5,1.85, height 2.4
FIDUCIAL-1.5 [mil]
  rrect100% 40x40 smd paste-100: 1(0,0)
  Top keep-out circle w5: c0,0 r39.37
HTS221 [mm]
  rrect50% 0.38x0.36 smd: 1(-0.5,-0.735) 2(0.5,-0.735) 4(0.5,0.735) 5(-0.5,0.735)
  rrect50% 0.36x0.38 smd: 3(0.735,0) 6(-0.735,0)
  body extent -1,-1 1,1, height 0.9
LEDC1608X80N-AK [mm]
  rrect50% 0.72x0.87 smd: A(0.725,0) C(-0.725,0)
  body extent -0.8,-0.4 0.8,0.4, height 0.79
LPS22H [mm]
  rrect50% 0.28x0.33 smd: 1(-0.25,-0.745) 2(0.25,-0.745) 6(0.25,0.745) 7(-0.25,0.745)
  rrect50% 0.33x0.28 smd: 3(0.745,-0.5) 4(0.745,0) 5(0.745,0.5) 8(-0.745,0.5) 9(-0.745,0) 10(-0.745,-0.5)
  body extent -1,-1 1,1, height 0.8
MKRSHIELD [mm]
  rect 1x2.5 smd: 0(42.516,1.068) 1(45.056,3.608) 2(47.596,1.068) 3(50.136,3.608) 4(52.676,1.068) 5(55.216,3.608) 5V(22.196,21.388) 6(55.216,23.928) 7(52.676,21.388) 8(50.136,23.928) 9(47.596,21.388) 10(45.056,23.928) 11(42.516,21.388) 12(39.976,23.928) 13(37.436,21.388) 14(34.896,23.928) A0(24.736,3.608) A1(27.276,1.068) A2(29.816,3.608) A3(32.356,1.068) A4(34.896,3.608) A5(37.436,1.068) A6(39.976,3.608) AREF(22.196,1.068) GND(29.816,23.928) RST(32.356,21.388) VCC(27.276,21.388) VIN(24.736,23.928)
"New footprint 1" [mm]
  rect 1x5.5 smd: 1(-1,-4.75) 2(1,-4.75)
  rect 1.6x3 smd: MP1(-3.4,-2.5) MP2(3.4,-2.51)
  body extent -3.97,-6.91 3.97,0.09, height 6.6
QFN65P200X200X80_HS-7L [mm] "QFN, 6-Leads, Body 2.00x2.00mm, Pitch 0.65mm, Thermal Pad 1.7X1.1mm, IPC High Density"
  rrect50% 0.4x0.45 smd: 1(-0.65,-0.925) 2(0,-0.925) 3(0.65,-0.925) 4(0.65,0.925) 5(0,0.925) 6(-0.65,0.925)
  rrect50% 1.6x1 smd: 7(0,0)
  silkscreen extent -1.35,-1.35 -1.25,-1.25, body extent -1,-1 1,1, height 0.8
RES-0402 [mm] "Chip Resistor, 2-Leads, Body  0402 (in) 1005 (mm), IPC Medium Density"
  rrect51% 0.55x0.58 smd mask+0: 1(-0.475,0) 2(0.475,0)
  body extent -0.5,-0.25 0.5,0.25, height 0.34
SFV24R-1STBE1HLF-Footprint-1 [mm]
  rrect50% 0.3x1.4 smd: 1(-5.75,0) 2(-5.25,0) 3(-4.75,0) 4(-4.25,0) 5(-3.75,0) 6(-3.25,0) 7(-2.75,0) 8(-2.25,0) 9(-1.75,0) 10(-1.25,0) 11(-0.75,0) 12(-0.25,0) 13(0.25,0) 14(0.75,0) 15(1.25,0) 16(1.75,0) 17(2.25,0) 18(2.75,0) 19(3.25,0) 20(3.75,0) 21(4.25,0) 22(4.75,0) 23(5.25,0) 24(5.75,0)
  rrect50% 0.3x1.4 smd paste+0 mask+0: MP1(-7.239,-1.016) MP2(7.239,-1.016)
  Top region: 6.2,0 6.2,-2.3 7.45,-2.3 7.45,-1.6 8.85,-1.6 8.85,-0.5 8.15,-0.5 8.15,0
  Top region: -6.2,0 -6.2,-2.3 -7.45,-2.3 -7.45,-1.6 -8.85,-1.6 -8.85,-0.5 -8.15,-0.5 -8.15,0
  body extent -8.75,-4.39 8.75,0.51, height 1.8
SOD123 [mm]
  rrect51% 0.91x0.97 smd paste+0 mask+0: A(1.505,0) C(-1.505,0)
  body extent -1.75,-0.85 1.75,0.85, height 1
SOD123-1 [mm]
  rrect50% 0.91x1.22 smd: A(1.635,0) C(-1.635,0)
  body extent -1.78,-0.78 1.92,0.82, height 1.27
SOT23 [mm]
  rect 1x1.4 smd: 1(-0.95,-1.1) 2(0.95,-1.1) 3(0,1.1)
  body extent -1.5,-1.25 1.5,1.25, height 1.05
SOT363 [mm]
  rrect50% 0.5x0.6 smd: 1(-0.75,-0.9) 3(0.75,-0.9) 4(0.75,0.9) 6(-0.75,0.9)
  rrect50% 0.4x0.6 smd: 2(0,-0.9) 5(0,0.9)
  silkscreen extent -1.62,-0.86 -1.42,-0.66, body extent -1.05,-1.15 1.05,1.15, height 1
SRR0604-100ML-Footprint-1 [mm]
  rect 1.65x2.5 smd: 1(-2.625,0) 2(2.625,0)
  body extent -3.25,-3.25 3.25,3.25, height 4.63
VFLGA14 [mm]
  rect 0.45x0.25 smd: 1(-1.175,0.75) 2(-1.175,0.25) 3(-1.175,-0.25) 4(-1.175,-0.75) 8(1.175,-0.75) 9(1.175,-0.25) 10(1.175,0.25) 11(1.175,0.75)
  rect 0.25x0.45 smd: 5(-0.5,-0.925) 6(0,-0.925) 7(0.5,-0.925) 12(0.5,0.925) 13(0,0.925) 14(-0.5,0.925)
  Top keep-out region: -0.83,-0.98 -0.83,-0.58 -0.74,-0.58 -0.74,-0.98
  Top keep-out region: 0.74,-0.98 0.74,-0.58 0.83,-0.58 0.83,-0.98
  Top keep-out region: 0.74,0.58 0.74,0.98 0.83,0.98 0.83,0.58
  Top keep-out region: -0.83,0.58 -0.83,0.98 -0.74,0.98 -0.74,0.58
  Top keep-out region: -1.5,-1.25 -1.5,-0.98 -0.74,-0.98 -0.74,-1.25
  Top keep-out region: 0.74,-1.25 0.74,-0.98 1.5,-0.98 1.5,-1.25
  Top keep-out region: 0.74,0.98 0.74,1.25 1.5,1.25 1.5,0.98
  Top keep-out region: -1.5,0.98 -1.5,1.25 -0.74,1.25 -0.74,0.98
  Top keep-out region: -0.83,-0.58 -0.83,0.58 0.83,0.58 0.83,-0.58
  Top keep-out lines w0.01: 1.4,-0.5 0.67,-0.5 ; 1.4,0 0.67,0 ; 1.4,0.5 0.67,0.5 ; 0.25,-1.15 0.25,-0.42 ; 0.25,0.42 0.25,1.15 ; -0.25,-1.15 -0.25,-0.42 ; -0.25,0.42 -0.25,1.15 ; -0.67,-0.5 -1.4,-0.5 ; -0.67,0 -1.4,0 ; -0.67,0.5 -1.4,0.5
  body extent -1.5,-1.25 1.5,1.25, height 0.76

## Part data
"Battery Holder1": library part UT0019-A.1, "Battery holder marker"
C1: library part C0008-A.3, "CAP CHIP 0402 10nF 25V X7R 10%", Case Code (Imperial)=0402, Case Code (Metric)=1005, Dielectric=X7R, Manufacturer=KEMET, Manufacturer 2=AVX, Manufacturer Part Number 2=04023C103KAT2A, Tolerance=10%, Voltage=25V
C2: library part C0037-A.3, "CAP CHIP 0402 4.7uF 6V3 X5R 20%", Case Code (Imperial)=0402, Case Code (Metric)=1005, Dielectric=X5R, Manufacturer=Murata, Tolerance=20%, Voltage=6.3V
C3 C4 C8 C10 C11 C12 C13: library part C0014-A.3, "CAP CHIP 0402 100nF 25V X5R 10%", Case Code (Imperial)=0402, Case Code (Metric)=1005, Dielectric=X5R, Manufacturer=KEMET, Manufacturer 2=AVX, Manufacturer Part Number 2=04023D104KAT2A, Tolerance=10%, Voltage=25V
C5: library part C0084-A.1, "CAP CHIP 0805 1uF 100V X7S 10%", Case Code (Imperial)=0805, Case Code (Metric)=2012, Dielectric=X7S, Manufacturer=Murata, Tolerance=10%, Voltage=100V
C6: library part C0019-A.3, "CAP CHIP 0402 1uF 6V3 X5R 20%", Case Code (Imperial)=0402, Case Code (Metric)=1005, Dielectric=X5R, Manufacturer=KEMET, Manufacturer 2=AVX, Manufacturer Part Number 2=04026D105MAT4A, Tolerance=20%, Voltage=6.3V
C7: library part C0088-A.2, "CAP CHIP 0402 220nF 6.3V X5R 10%", Capacitance=220nF, Case Code (Imperial)=0402, Case Code (Metric)=1005, Dielectric=X5R, Dielectric Material=Ceramic, Manufacturer=KEMET, Max Operating Temperature=85°C, Min Operating Temperature=-55°C, Package Quantity=1, Tolerance=10%, Voltage=6.3V
C9 C14: library part C0018-A.3, "CAP CHIP 0402 1uF 16V X5R 10%", Case Code (Imperial)=0402, Case Code (Metric)=1005, Dielectric=X5R, Manufacturer=KEMET, Manufacturer 2=AVX, Manufacturer Part Number 2=0402YD105KAT2A, Tolerance=10%, Voltage=16V
D1 D2: library part D0035-A.2, "DIODE SCHOTTKY SMD 2A 60V SOD123", Manufacturer=Nexperia
D3: library part D0029-A.2, "DIODE FAST SMD 200mA 100V SOD123", Manufacturer=Vishay
DL1: library part L0009-A.3, "LED SMD 0603 GREEN/568 15mcd 120^", Manufacturer=Broadcom
DL2 DL3: library part L0001-A.2, "LED SMD 0805 YELLOW CLEAR", Manufacturer=Kingbright, Manufacturer 2=Lite-On, Manufacturer Part Number 2=LTST-C170YKT
FD1 FD2 FD3 FD4 FD5 FD6: library part UT0000-A.2
HS-1: library part U0006-A.3, "SENS HUMIDITY 6% 3.6V", Manufacturer=STMicroelectronics, Max Supply Voltage=3.6V, Min Operating Temperature=-40, Min Supply Voltage=1.7V
J1: library part J0011-A.1, "CONN Micro SD", Manufacturer=Amphenol
J2 J3 J4: library part J0114-A.4, "CONN GROVE SMD-90D(4+2P-2.0) 320110032", Manufacturer=Seeed, Manufacturer 2=4UCONN, Manufacturer Part Number 2=215TW-511
J6: library part J0028-A.2, "CONN FPC/FFC 41POS .3MM", Current Rating=200mA, Flammability Rating="UL94 HB", Manufacturer=Hirose, Max Operating Temperature=85°C, Min Operating Temperature=-55°C, Voltage Rating=30V
J7 J8: library part J0053-A.3, "CONN BATTERY HOLDER 18650 CLIP SMT", Manufacturer="Keystone Electronics"
J9 J10: library part J0110-A.2, "CONN TERM BLK 3POS R/A 2.5MM SMD", Color=Black, Current=5A, Current Rating=6A, Flammability Rating="UL94 V-0", Manufacturer="Phoenix Contact", Package Quantity=770, Voltage=150V, Voltage Rating=160V
J11: library part J0103-A.2, "CONN HEADER SMD 2 POS 0.079\" (2.00mm)", Manufacturer=JST, Part Number=B2B-PH-SM4-TBLFSN
J12: library part J0102-A.1, "CONN FPC SMD SKT 24 POS 0.5mm RA SMD", Contact Resistance=30mR, Current Rating=500mA, Flammability Rating="UL94 V-0", Housing Color=Black, Insulation Resistance=100MR, Manufacturer="Amphenol FCI", Max Operating Temperature=105°C, Max Voltage Rating (AC)=50V, Min Operating Temperature=-55°C, Package Quantity=3000
JANALOG1: library part J0098-A.4, "CONN STRIP SMD MKR F AREF"
JDIGITAL1: library part J0099-A.5, "CONN STRIP SMD MKR F 5V"
L0 L1 L2 L3 L4: library part L0003-A.7, "LED RGB 2020", Manufacturer="Shenzhen LED Color Opto Electronic CO.,LTD."
L6: library part I0013-A.2, "FIXED IND 10UH 1.3A 120 MOHM SMD", DC Resistance (DCR)=120mR, Frequency=30MHz, Manufacturer=Bourns, Max DC Current=1.3A, Max Operating Temperature=125°C, Min Operating Temperature=-40°C, Package Quantity=1000, Test Frequency=2.52MHz, Tolerance=20%
LPS-1: library part U0009-A.4, "SENSOR PRESSURE 3.77 PSI ~ 18.27 PSI (26 kPa ~ 126 kPa) Absolute 24 b 10-WFLGA", Manufacturer=STMicroelectronics
M1: library part S0011-A.3, "BUZZER 2 V, 4 V, 100 mA, 85 dB", Manufacturer="Multicomp Pro", Manufacturer 2=DB, Manufacturer Part Number 2=CDT092A3BILFMP-002
MKR1: library part UT0017-A.3, "MKR board SMD pads alternate"
Q1: library part T0004-A.2, "MOSFET N-CH 60V 300mA SOT23", Manufacturer="On Semiconductor"
Q2: library part T0012-A.3, "MOSFET N-CH 2x 60V 0.32A SOT363", Manufacturer=Nexperia
R1 R2 R4 R5 R10 R11 R12 R16 R19 R23: library part R0004-A.3, "RES CHIP 0402 10K 5% 1/16W", Case Code (Imperial)=0402, Case Code (Metric)=1005, Manufacturer=Vishay, Manufacturer 2=Panasonic, Manufacturer Part Number 2=ERJ-2GEJ103X, Power=63mW, Tolerance=5%
R3: library part R0017-A.3, "RES CHIP 0402 330R 5% 1/16W", Case Code (Imperial)=0402, Case Code (Metric)=1005, Manufacturer=Vishay, Manufacturer 2=Panasonic, Manufacturer Part Number 2=ERJ-2GEJ331X, Power=63mW, Tolerance=5%
R6 R7: library part R0016-A.3, "RES CHIP 0402 270R 5% 1/16W", Case Code (Imperial)=0402, Case Code (Metric)=1005, Manufacturer=Yageo, Power=63mW, Tolerance=5%
R8 R9 R13 R14 R15 R17 R18 R20 R22 R24 R25 R26 R27: library part R0000-A.3, "RES CHIP 0402 0R 1/16W", Case Code (Imperial)=0402, Case Code (Metric)=1005, Manufacturer=Vishay, Manufacturer 2=Panasonic, Manufacturer Part Number 2=ERJ-S020R00X, Power=63mW, Tolerance=J
R21: library part R0170-A.1, "RES CHIP 0402 10 OHM 1/16W 1%", Case Code (Imperial)=0402, Case Code (Metric)=1005, Manufacturer=Yageo, Max Operating Temperature=155°C, Min Operating Temperature=-55°C, Power=63mW, Resistance=10R, Temperature Coefficient=100ppm/°C, Tolerance=1%, Voltage Rating=50V
R28: library part R0009-A.3, "RES CHIP 0402 22R 1% 1/16W", Case Code (Imperial)=0402, Case Code (Metric)=1005, Manufacturer=Yageo, Power=63mW, Tolerance=1%
S1 S2: library part S0009-A.4, "RELAY GEN PURPOSE DPDT 2A 250V", Coil Current=28mA, Coil Power=140mW, Coil Resistance=178R, Coil Voltage (DC)=5V, Contact Current Rating=2A, Manufacturer=KEMET, Max Operating Temperature=85°C, Max Voltage Rating (AC)=250V, Max Voltage Rating (DC)=220V, Min Operating Temperature=-40°C, Package Quantity=500
U1: library part U0010-A.3, "IMU ACCEL/GYRO I2C/SPI 14VFLGA", Case/Package=LGA, Manufacturer=STMicroelectronics, Max Operating Temperature=85°C, Max Supply Voltage=3.6V, Min Operating Temperature=-40°C, Min Supply Voltage=1.71V
U2: library part U0136-A.5, "IC SENS OPT 560NM AMBIENT MODULE APDS-9960", Manufacturer=Broadcom
U3: library part U0125-A.6, "IC LED BOOST DRIVER", Frequency=600kHz, Manufacturer="ON Semiconductor", Max Input Voltage=5.5V, Max Operating Temperature=85°C, Max Output Voltage=39V, Min Input Voltage=2.7V, Min Operating Temperature=-30°C, Min Output Voltage=37V, Nominal Input Voltage (DC)=3.6V, Output Current per Channel=700mA, Package Quantity=3000

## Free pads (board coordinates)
  round 0 hole 2.5 unplated: H1(-39.75,0) H2(19.875,34.425) H3(19.875,-34.425)
  round 2.35 smd far side: H8(35.5,-17.049) H9(19.5,-17.049) H10(-19.5,-17.049) H11(-35.5,-17.049)
  round 0 hole 0.5 unplated: T2(-31.923,-28.245) T2(-31.809,28.403) T2(-31.323,-28.945) T2(-31.209,29.103) T2(-30.662,-29.61) T2(-30.509,29.803) T2(-30.023,-30.245) T2(-29.909,30.403) T2(-29.423,-30.845) T2(-29.309,31.003) T2(29.296,30.991) T2(29.421,-30.7) T2(29.896,30.391) T2(30.021,-30.1) T2(30.496,29.791) T2(30.621,-29.5) T2(31.196,29.091) T2(31.321,-28.8) T2(31.796,28.391) T2(31.921,-28.1)

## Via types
v1: diameter 0.706, hole 0.3, Top to Bottom, tented both sides, 114 vias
